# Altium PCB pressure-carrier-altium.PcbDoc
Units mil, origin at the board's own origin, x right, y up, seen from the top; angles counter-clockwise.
Board outline 2200 x 1600 mil, 2 copper layers (Top, Bottom); 15 components, 7 nets, 41 pads, 9 vias.
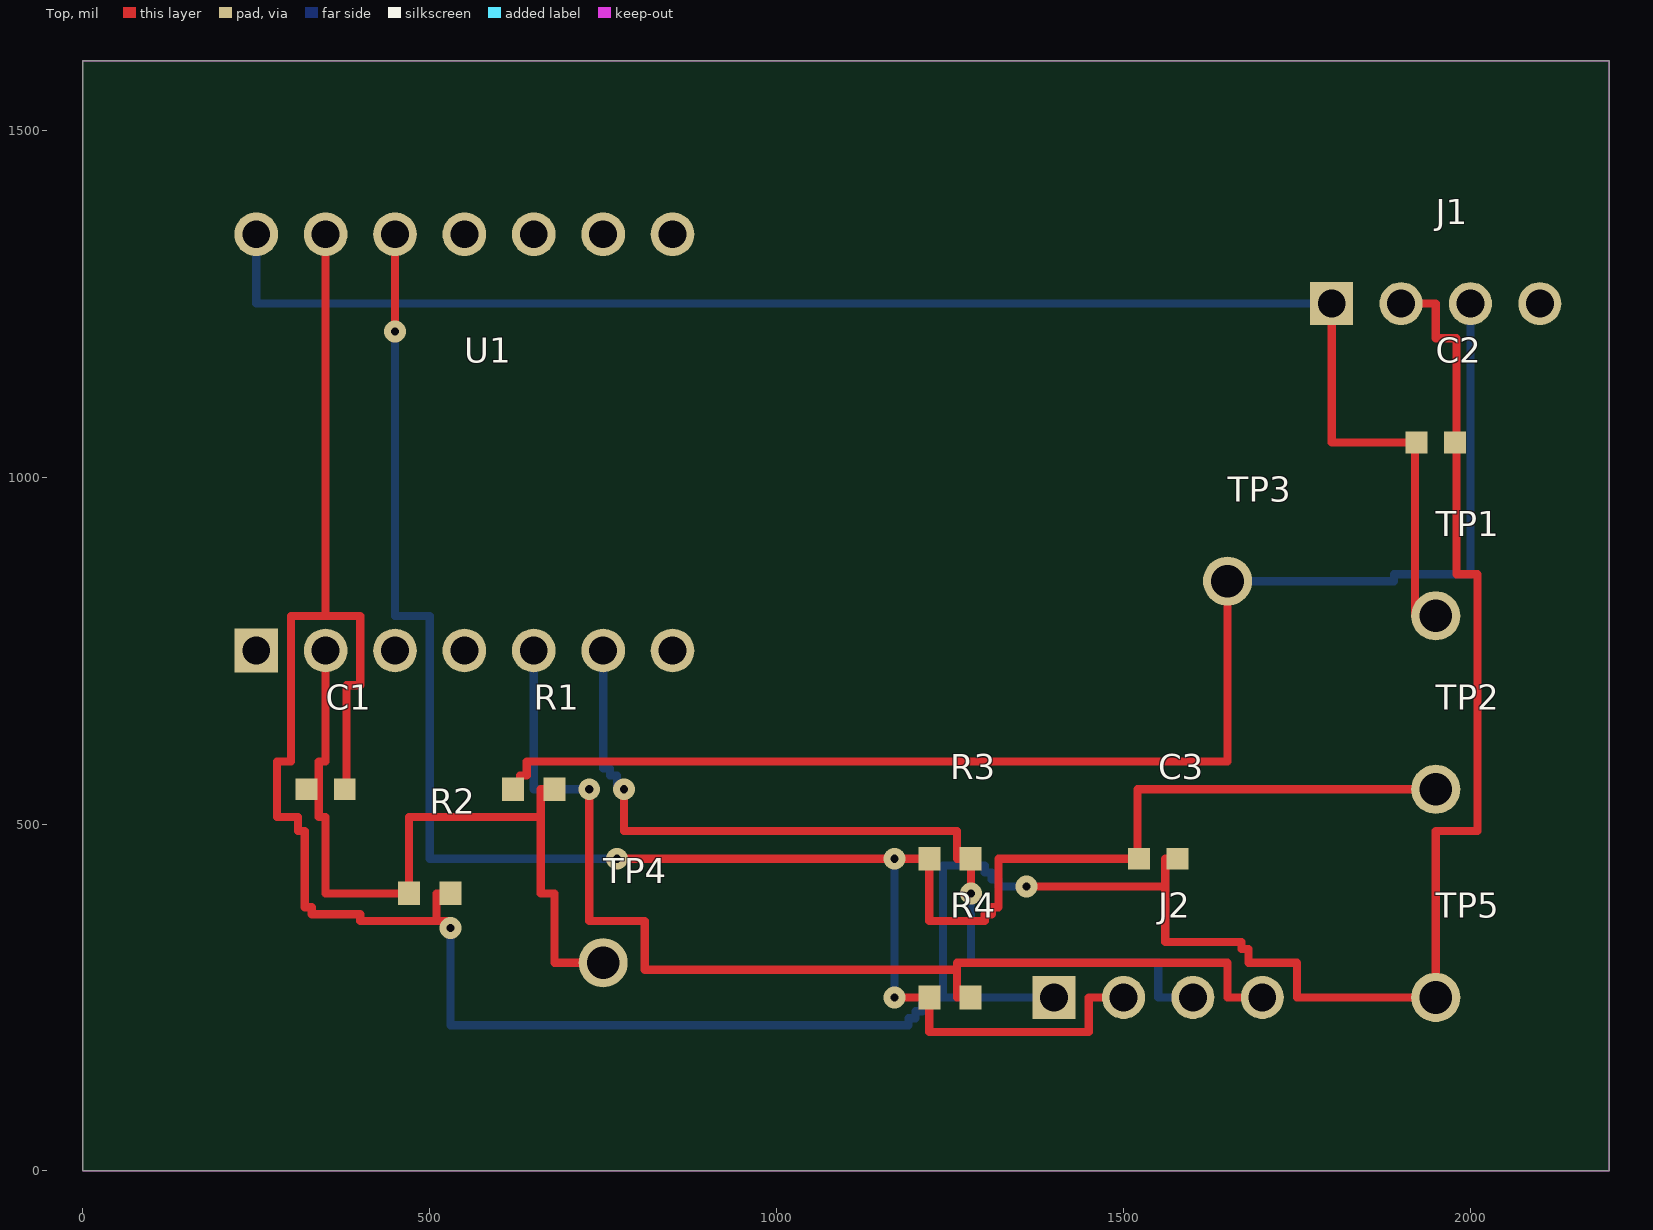
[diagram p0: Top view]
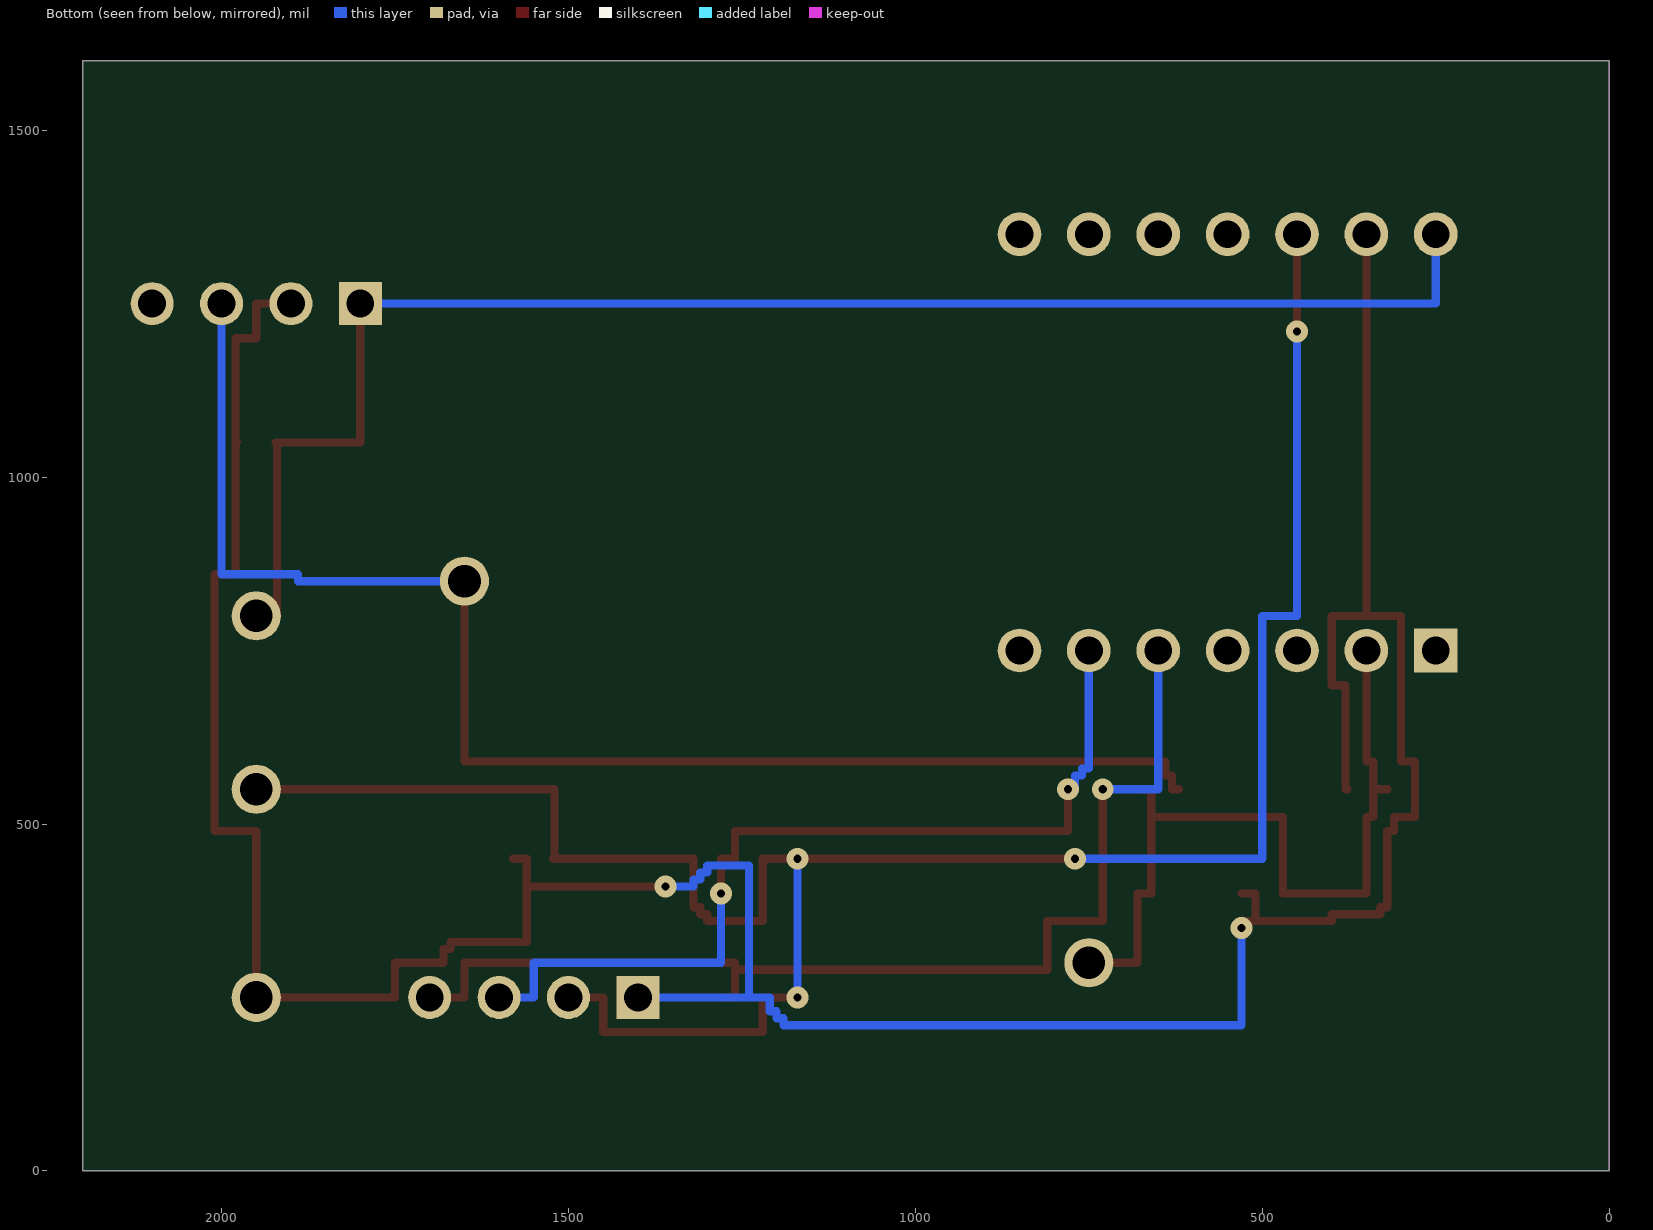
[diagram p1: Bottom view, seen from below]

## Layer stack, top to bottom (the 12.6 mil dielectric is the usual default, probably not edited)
Top Solder: solder mask 0.4, Solder Resist, Dk 3.5
Top: signal copper 1.4
Dielectric 1: dielectric 12.6, FR-4, Dk 4.8
Bottom: signal copper 1.4
Bottom Solder: solder mask 0.4, Solder Resist, Dk 3.5

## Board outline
0,1600 0,0 2200,0 2200,1600

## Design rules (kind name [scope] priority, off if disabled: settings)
BoardOutlineClearance mdCopperDimension [All] p1: gap=10 ignorepadtopadclearanceinfootprint=FALSE except(0: Arc-SplitContinuation Track-SplitContinuation SMDPad-SplitContinuation THPad-SplitContinuation Via-SplitContinuation Fill-SplitContinuation Poly-SplitContinuation Region-SplitContinuation Text-SplitContinuation; 19.68: Poly-OutlineEdge Poly-CavityEdge Poly-CutoutEdge Poly-SplitBarrior)
Clearance "Clearance (Same Net)" [All] p1: gap=10 ignorepadtopadclearanceinfootprint=FALSE
Clearance [All] p2: gap=10 ignorepadtopadclearanceinfootprint=FALSE
HoleSize [All] p1: absolutevalues=TRUE maxlimit=100000 minlimit=11.81 maxpercent=80.000 minpercent=20.000
MinimumSolderMaskSliver [All] p1 off: minsoldermaskwidth=10
PasteMaskExpansion mlMinCreamFrame [All] p1: expansion=0
PolygonConnect [All] p1: connectstyle=Relief reliefconductorwidth=10 reliefentries=4 polygonreliefangle="90 Angle" airgapwidth=10
RoutingVias [All] p1: holewidth=11.81 width=35.43 viastyle="Through Hole" minholewidth=11.81 minwidth=35.43 maxholewidth=100 maxwidth=100
SolderMaskExpansion mlMinStopFrame [All] p1: expansion=0 istentingtop=FALSE
Width [All] p1: maxlimit=10 minlimit=11.81 preferedwidth=11.81
27 further rules are at their usual default settings.

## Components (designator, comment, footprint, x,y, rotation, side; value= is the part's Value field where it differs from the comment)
C1 "" TDK_C1608_0603 350,550 r0 top
C2 "" TDK_C1608_0603 1950,1050 r0 top
C3 "" TDK_C1608_0603 1550,450 r0 top
J1 "" Samtec_TSW104_THT 1950,1250 r0 top
J2 "" Samtec_SSQ104_LL_THT 1550,250 r0 top
R1 "" YAGEO_RT0603_1608 650,550 r0 top
R2 "" YAGEO_RT0603_1608 500,400 r0 top
R3 "" YAGEO_AC0603_1608 1250,450 r0 top
R4 "" YAGEO_AC0603_1608 1250,250 r0 top
TP1 "" PCB_TestPad_PTH_1p2_D1p8 1950,800 r0 top
TP2 "" PCB_TestPad_PTH_1p2_D1p8 1950,550 r0 top
TP3 "" PCB_TestPad_PTH_1p2_D1p8 1650,850 r0 top
TP4 "" PCB_TestPad_PTH_1p2_D1p8 750,300 r0 top
TP5 "" PCB_TestPad_PTH_1p2_D1p8 1950,250 r0 top
U1 "" Seeed_XIAO_ESP32C3_THT 550,1050 r0 top

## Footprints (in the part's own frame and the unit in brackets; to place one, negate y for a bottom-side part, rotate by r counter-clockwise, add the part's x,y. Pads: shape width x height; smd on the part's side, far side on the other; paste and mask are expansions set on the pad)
PCB_TestPad_PTH_1p2_D1p8 [mil] "PCB_TestPad_PTH_1p2_D1p8"
  round 70.87 hole 47.24: 1(0,0)
Samtec_SSQ104_LL_THT [mil] "Samtec_SSQ104_LL_THT"
  rect 62x62 / inner round 57.28 / far side rect 62x62 hole 40.16: 1(-150,0)
  round 62 hole 40.16: 2(-50,0) 3(50,0) 4(150,0)
Samtec_TSW104_THT [mil] "Samtec_TSW104_THT"
  rect 62x62 / inner round 57.28 / far side rect 62x62 hole 40.16: 1(-150,0)
  round 62 hole 40.16: 2(-50,0) 3(50,0) 4(150,0)
Seeed_XIAO_ESP32C3_THT [mm] "Seeed_XIAO_ESP32C3_THT"
  rect 1.6x1.6 / inner round 1.6 / far side rect 1.6x1.6 hole 1.02: 1(-7.62,-7.62)
  round 1.6 hole 1.02: 2(-5.08,-7.62) 3(-2.54,-7.62) 4(0,-7.62) 5(2.54,-7.62) 6(5.08,-7.62) 7(7.62,-7.62) 8(7.62,7.62) 9(5.08,7.62) 10(2.54,7.62) 11(0,7.62) 12(-2.54,7.62) 13(-5.08,7.62) 14(-7.62,7.62)
TDK_C1608_0603 [mm] "TDK_C1608_0603"
  rect 0.8x0.8 smd: 1(-0.7,0) 2(0.7,0)
YAGEO_AC0603_1608 [mil] "YAGEO_AC0603_1608"
  rect 31.75x34.02 smd: 1(-29.66,0) 2(29.66,0)
YAGEO_RT0603_1608 [mil] "YAGEO_RT0603_1608"
  rect 31.75x34.02 smd: 1(-29.66,0) 2(29.66,0)

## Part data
C1 C2 C3: library part TDK_C1608_0603, PackageName=C0603
J1: library part Samtec_TSW104_THT, PackageName=HDR-M-2.54_1X4
J2: library part Samtec_SSQ104_LL_THT, PackageName=HDR-F-2.54_1X4
R1 R2: library part YAGEO_RT0603_1608, PackageName=R0603
R3 R4: library part YAGEO_AC0603_1608, PackageName=R0603
TP1 TP2 TP3 TP4 TP5: library part PCB_TestPad_PTH_1p2_D1p8, PackageName=TESTPOINT-TH_BD2.0-D1.0_TESTPOINT-TH_BD2.0-D1.0
U1: library part Seeed_XIAO_ESP32C3_THT, PackageName=DIP-14_L17.8-W17.8-P2.54-LS15.2-BL

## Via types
v1: diameter 31.5/31.5 (per signal layer), hole 11.81, Top to Bottom, 9 vias

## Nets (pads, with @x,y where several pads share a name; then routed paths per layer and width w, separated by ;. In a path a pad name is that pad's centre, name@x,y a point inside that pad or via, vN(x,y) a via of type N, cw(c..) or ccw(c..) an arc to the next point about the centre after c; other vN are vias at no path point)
3V3: C3.1 J2.2 R3.1 R4.1 TP2.1 U1.12 | length 3313.1
  Top w11.81: v1(450,1210) U1.12 ; v1(770,450) R3.1 ; v1(1170,250) R4.1 ; R4.1@1220,250 1220,200 1450,200 1450,250 J2.2 ; R3.1@1220,450 1220,360 1300,360 1300,370 1310,370 1310,380 1320,380 1320,450 C3.1 ; C3.1@1520,450 1520,550 TP2.1
  Bottom w11.81: v1(450,1210) 450,800 500,800 500,450 v1(770,450) ; v1(1170,250) v1(1170,450)
ADC_PRESSURE: C1.1 R1.2 R2.1 TP4.1 U1.2 | length 1173.1
  Top w11.81: C1.1 320,550 340,550 ; U1.2 350,590 340,590 340,550 ; R2.1@470,400 470,510 660,510 ; R2.1 350,400 350,510 340,510 340,550 ; R1.2 680,550 660,550 660,510 ; TP4.1 680,300 680,400 660,400 660,510
GND: C1.2 C2.2 C3.2 J1.2 J2.1 R2.2 TP5.1 U1.13 | length 5077.7
  Top w11.81: U1.13 350,800 ; C1.2 380,550 380,700 400,700 400,800 350,800 ; R2.2 530,400 510,400 510,360 ; v1(530,350) 530,360 510,360 ; v1(1360,410) 1560,410 ; C3.2 1580,450 1560,450 1560,410 ; J1.2 1950,1250 1950,1200 1980,1200 C2.2@1980,1050 ; C2.2 C2.2@1980,1050 ; 350,800 300,800 300,590 280,590 280,510 310,510 310,490 320,490 320,380 330,380 330,370 400,370 400,360 510,360 ; 1560,410 1560,330 1670,330 1670,320 1680,320 1680,300 1750,300 1750,250 TP5.1 1950,490 2010,490 2010,860 1980,860 C2.2@1980,1050
  Bottom w11.81: v1(530,350) 530,210 1190,210 1190,220 1200,220 1200,230 1210,230 1210,250 J2.1 ; 1240,250 1240,440 1300,440 1300,430 1310,430 1310,420 1320,420 1320,410 v1(1360,410)
I2C_SCL: J2.3 R3.2 U1.6 | length 1350.3
  Top w11.81: v1(780,550) 780,490 1260,490 1260,450 R3.2@1280,450 ; R3.2 R3.2@1280,450 ; v1(1280,400) R3.2@1280,450
  Bottom w11.81: U1.6 750,580 760,580 760,570 770,570 770,550 v1(780,550) ; v1(1280,400) 1280,300 1550,300 1550,250 J2.3
I2C_SDA: J2.4 R4.2 U1.5 | length 1630.3
  Top w11.81: v1(730,550) 730,360 810,360 810,290 1260,290 ; R4.2 1280,250 1260,250 1260,290 ; J2.4 1650,250 1650,300 1260,300 1260,290
  Bottom w11.81: U1.5 650,550 v1(730,550)
SENSOR_OUT: J1.3 R1.1 TP3.1 | length 2080.3
  Top w11.81: R1.1 620,550 630,550 630,570 640,570 640,590 1650,590 TP3.1
  Bottom w11.81: TP3.1 1890,850 1890,860 2000,860 J1.3
USB_5V: C2.1 J1.1 TP1.1 U1.14 | length 2252.4
  Top w11.81: J1.1 1800,1050 C2.1 ; C2.1@1920,1050 1920,800 TP1.1
  Bottom w11.81: U1.14 250,1250 J1.1
pads on no net: J1.4 U1.1 U1.3 U1.4 U1.7 U1.8 U1.9 U1.10 U1.11

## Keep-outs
Keep-Out Layer:
  the board outline again, w0

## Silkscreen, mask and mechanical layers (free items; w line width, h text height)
Dimension:
  the board outline again, w0
tPlace:
  text "PRESSURE / XIAO CARRIER" at 78.74,1481.89 h73.22
  text "REV A / USB 5V / 2-LAYER" at 78.74,78.74 h54.92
